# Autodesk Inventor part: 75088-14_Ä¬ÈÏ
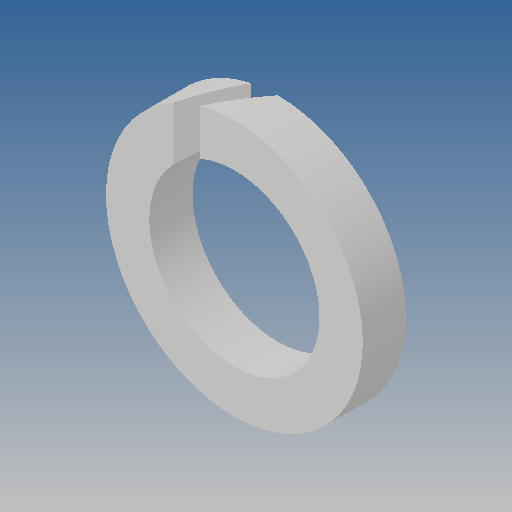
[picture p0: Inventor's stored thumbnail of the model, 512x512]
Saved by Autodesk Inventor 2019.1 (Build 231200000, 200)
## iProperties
Created: 2010-06
Part Number: 75088-14_Ä¬ÈÏ
Material: Ogólny
Document SubType Name: Modeling
Designer: CADENGINEERING4
Density: 1 g/cm^3
Appearance: Domyślna
Author: CADENGINEERING4
Revision Number: ÈÎºÎ
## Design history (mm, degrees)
feature "NONE"
node "Bryła1"
